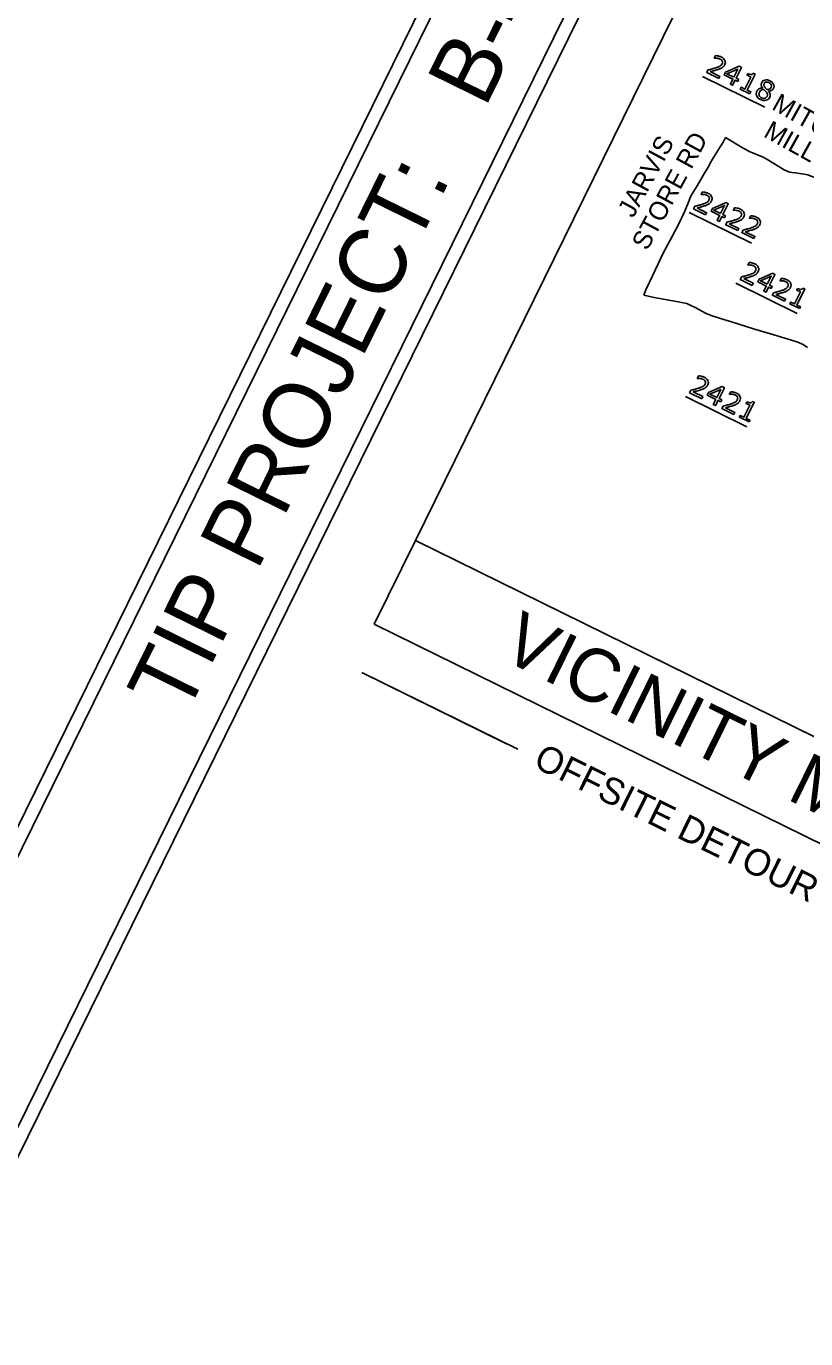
# Model space of a CAD drawing. Extents: x 1428128 to 1430390, y 857947 to 859822.
# Drawn here: x 1428792.5 to 1429086, y 858941.1 to 859435.3 of the extents above; entities that cross this region are included whole.
import ezdxf

# ---------------------------------------------------------------- set-up
doc = ezdxf.new("R2010")
doc.units = 0
for name, color, linetype in [('Old_Level_1', 7, 'Continuous'), ('Sheet Data Field CELL', 7, 'Continuous'), ('Sheet Title CELL', 7, 'Continuous')]:
    doc.layers.add(name, color=color, linetype=linetype)

msp = doc.modelspace()

# ---------------------------------------------------------------- linework, layer by layer
at = {"layer": 'Old_Level_1'}
for p, q in [((1429047.11, 859416.46), (1429070.63, 859404.89)), ((1429042.15, 859365.13), (1429065.62, 859353.58)), ((1429059.72, 859338.55), (1429082.81, 859327.18)), ((1429040.69, 859295.86), (1429063.78, 859284.5)), ((1428918.89, 859191.97), (1428973.38, 859165.16))]:
    msp.add_line(p, q, dxfattribs=at)
for points in [[(1429051.64, 859423.3), (1429051.59, 859423.32), (1429052.06, 859424.27)], [(1429053.28, 859415.66), (1429048.72, 859417.9), (1429049.19, 859418.85)], [(1429050.04, 859418.22), (1429053.66, 859416.44), (1429053.28, 859415.66)], [(1429060.43, 859414.49), (1429059.43, 859414.99), (1429058.49, 859413.09), (1429057.63, 859413.52), (1429058.56, 859415.41), (1429055.33, 859417), (1429055.84, 859418.04), (1429060.97, 859420.23), (1429061.8, 859419.82), (1429059.78, 859415.71), (1429060.78, 859415.22), (1429060.43, 859414.49)], [(1429058.91, 859416.14), (1429060.41, 859419.18), (1429056.3, 859417.42), (1429058.91, 859416.14)], [(1429066.27, 859417.65), (1429066.97, 859417.31), (1429063.98, 859411.24), (1429065.36, 859410.57), (1429065.02, 859409.88)], [(1429065.02, 859409.88), (1429061.38, 859411.67), (1429061.71, 859412.36), (1429063.11, 859411.67), (1429065.33, 859416.18), (1429063.93, 859416.87), (1429064.24, 859417.48)], [(1429069.74, 859412.02), (1429069.76, 859412.04)], [(1429071.97, 859410.91), (1429071.96, 859410.88)], [(1429046.68, 859371.97), (1429046.63, 859371.99), (1429047.1, 859372.94)], [(1429055.47, 859363.16), (1429054.47, 859363.65), (1429053.54, 859361.76), (1429052.67, 859362.18), (1429053.6, 859364.08), (1429050.38, 859365.66), (1429050.89, 859366.7), (1429056.01, 859368.89), (1429056.85, 859368.49), (1429054.82, 859364.38), (1429055.82, 859363.88), (1429055.47, 859363.16)], [(1429048.32, 859364.32), (1429043.76, 859366.57), (1429044.23, 859367.52)], [(1429045.08, 859366.89), (1429048.7, 859365.1), (1429048.32, 859364.32)], [(1429053.96, 859364.8), (1429055.45, 859367.84), (1429051.35, 859366.09), (1429053.96, 859364.8)], [(1429058.8, 859366), (1429058.76, 859366.02), (1429059.22, 859366.97)], [(1429064.87, 859363.02), (1429064.82, 859363.04), (1429065.29, 859363.99)], [(1429060.44, 859358.36), (1429055.88, 859360.6), (1429056.35, 859361.55)], [(1429057.2, 859360.92), (1429060.83, 859359.14), (1429060.44, 859358.36)], [(1429066.51, 859355.37), (1429061.95, 859357.62), (1429062.42, 859358.57)], [(1429063.27, 859357.94), (1429066.89, 859356.15), (1429066.51, 859355.37)], [(1429064.25, 859345.38), (1429064.21, 859345.41), (1429064.67, 859346.35)], [(1429065.89, 859337.74), (1429061.33, 859339.98), (1429061.8, 859340.93)], [(1429062.65, 859340.3), (1429066.28, 859338.52), (1429065.89, 859337.74)], [(1429073.04, 859336.58), (1429072.04, 859337.07), (1429071.11, 859335.17), (1429070.24, 859335.6), (1429071.17, 859337.49), (1429067.95, 859339.08), (1429068.46, 859340.12), (1429073.59, 859342.31), (1429074.42, 859341.9), (1429072.4, 859337.79), (1429073.4, 859337.3), (1429073.04, 859336.58)], [(1429071.53, 859338.22), (1429073.03, 859341.26), (1429068.92, 859339.5), (1429071.53, 859338.22)], [(1429076.38, 859339.42), (1429076.33, 859339.44), (1429076.8, 859340.39)], [(1429078.02, 859331.77), (1429073.46, 859334.02), (1429073.93, 859334.97)], [(1429074.78, 859334.34), (1429078.4, 859332.55), (1429078.02, 859331.77)], [(1429083.7, 859328.98), (1429080.05, 859330.77), (1429080.39, 859331.46), (1429081.79, 859330.77), (1429084.01, 859335.28), (1429082.61, 859335.97), (1429082.91, 859336.58)], [(1429084.94, 859336.75), (1429085.65, 859336.41), (1429082.66, 859330.34), (1429084.03, 859329.67), (1429083.7, 859328.98)], [(1429045.22, 859302.7), (1429045.17, 859302.72), (1429045.64, 859303.67)], [(1429054.01, 859293.89), (1429053.01, 859294.39), (1429052.08, 859292.49), (1429051.21, 859292.92), (1429052.14, 859294.81), (1429048.92, 859296.4), (1429049.43, 859297.44), (1429054.56, 859299.63), (1429055.39, 859299.22), (1429053.37, 859295.11), (1429054.37, 859294.62), (1429054.01, 859293.89)], [(1429046.86, 859295.06), (1429042.3, 859297.3), (1429042.77, 859298.25)], [(1429043.62, 859297.62), (1429047.24, 859295.84), (1429046.86, 859295.06)], [(1429052.5, 859295.54), (1429053.99, 859298.58), (1429049.89, 859296.82), (1429052.5, 859295.54)], [(1429057.35, 859296.74), (1429057.3, 859296.76), (1429057.77, 859297.71)], [(1429065.91, 859294.07), (1429066.61, 859293.72), (1429063.63, 859287.66), (1429065, 859286.98), (1429064.66, 859286.3)], [(1429058.99, 859289.09), (1429054.43, 859291.33), (1429054.9, 859292.29)], [(1429055.75, 859291.65), (1429059.37, 859289.87), (1429058.99, 859289.09)], [(1429064.66, 859286.3), (1429061.02, 859288.09), (1429061.36, 859288.78), (1429062.76, 859288.09), (1429064.98, 859292.6), (1429063.58, 859293.29), (1429063.88, 859293.9)]]:
    msp.add_lwpolyline(points, dxfattribs=at)
for points in [[(1429049.19, 859418.85), (1429049.86, 859419.03), (1429050.54, 859419.2), (1429051.22, 859419.37), (1429051.83, 859419.57), (1429053.11, 859419.98), (1429053.67, 859420.32), (1429054.24, 859420.65), (1429054.52, 859421.23), (1429054.78, 859421.75), (1429054.58, 859422.22), (1429054.38, 859422.68), (1429053.76, 859422.99), (1429053.34, 859423.19), (1429052.79, 859423.28), (1429052.24, 859423.37), (1429051.64, 859423.3)], [(1429052.06, 859424.27), (1429052.46, 859424.27), (1429053.06, 859424.14), (1429053.66, 859424.01), (1429054.16, 859423.76), (1429055.2, 859423.25), (1429055.54, 859422.46), (1429055.88, 859421.67), (1429055.46, 859420.82), (1429055.27, 859420.43), (1429055.01, 859420.15), (1429054.75, 859419.87), (1429054.41, 859419.66), (1429054.1, 859419.47), (1429053.73, 859419.31), (1429053.36, 859419.16), (1429052.86, 859419), (1429052.14, 859418.76), (1429051.41, 859418.57), (1429050.67, 859418.38), (1429050.04, 859418.22)], [(1429064.24, 859417.48), (1429064.52, 859417.34), (1429064.87, 859417.23), (1429065.22, 859417.12), (1429065.43, 859417.13), (1429065.69, 859417.14), (1429065.9, 859417.25), (1429066.1, 859417.37), (1429066.27, 859417.65)], [(1429069.76, 859412.04), (1429069.36, 859412.6), (1429069.26, 859413.07), (1429069.17, 859413.54), (1429069.43, 859414.06), (1429069.8, 859414.82), (1429070.67, 859415.02), (1429071.55, 859415.22), (1429072.51, 859414.74), (1429073.52, 859414.25), (1429073.88, 859413.47), (1429074.24, 859412.69), (1429073.88, 859411.94), (1429073.65, 859411.49), (1429073.15, 859411.19), (1429072.65, 859410.89), (1429071.97, 859410.91)], [(1429072.98, 859412.37), (1429073.22, 859412.85), (1429072.99, 859413.33), (1429072.76, 859413.8), (1429072.18, 859414.08), (1429071.61, 859414.36), (1429071.11, 859414.27), (1429070.61, 859414.18), (1429070.38, 859413.72), (1429070.22, 859413.39), (1429070.29, 859413.06), (1429070.36, 859412.74), (1429070.64, 859412.37), (1429070.76, 859412.21), (1429071.01, 859411.92), (1429071.26, 859411.63), (1429071.52, 859411.4), (1429072.12, 859411.48), (1429072.45, 859411.71), (1429072.78, 859411.95), (1429072.98, 859412.37)], [(1429072.44, 859408.56), (1429072.01, 859407.69), (1429071.04, 859407.44), (1429070.08, 859407.2), (1429069.05, 859407.71), (1429067.95, 859408.24), (1429067.58, 859409.13), (1429067.21, 859410.01), (1429067.64, 859410.89), (1429067.92, 859411.46), (1429068.47, 859411.75), (1429069.02, 859412.04), (1429069.74, 859412.02)], [(1429071.47, 859408.93), (1429071.67, 859409.35), (1429071.61, 859409.69), (1429071.55, 859410.03), (1429071.14, 859410.54), (1429070.98, 859410.75), (1429070.77, 859410.96), (1429070.56, 859411.17), (1429070.21, 859411.53), (1429069.7, 859411.51), (1429069.26, 859411.25), (1429068.83, 859410.99), (1429068.6, 859410.51), (1429068.3, 859409.9), (1429068.52, 859409.3), (1429068.75, 859408.69), (1429069.39, 859408.38), (1429070.05, 859408.05), (1429070.61, 859408.2), (1429071.18, 859408.34), (1429071.47, 859408.93)], [(1429071.96, 859410.88), (1429072.46, 859410.3), (1429072.6, 859409.74), (1429072.74, 859409.17), (1429072.44, 859408.56)], [(1429044.23, 859367.52), (1429044.9, 859367.69), (1429045.58, 859367.86), (1429046.26, 859368.03), (1429046.87, 859368.23), (1429048.15, 859368.64), (1429048.72, 859368.98), (1429049.28, 859369.32), (1429049.56, 859369.89), (1429049.82, 859370.42), (1429049.62, 859370.88), (1429049.42, 859371.35), (1429048.8, 859371.65), (1429048.39, 859371.86), (1429047.83, 859371.95), (1429047.28, 859372.04), (1429046.68, 859371.97)], [(1429047.1, 859372.94), (1429047.5, 859372.94), (1429048.1, 859372.8), (1429048.7, 859372.67), (1429049.2, 859372.42), (1429050.24, 859371.91), (1429050.58, 859371.13), (1429050.92, 859370.34), (1429050.5, 859369.48), (1429050.31, 859369.1), (1429050.05, 859368.82), (1429049.79, 859368.53), (1429049.46, 859368.33), (1429049.14, 859368.13), (1429048.77, 859367.98), (1429048.4, 859367.83), (1429047.9, 859367.66), (1429047.18, 859367.43), (1429046.45, 859367.24), (1429045.71, 859367.04), (1429045.08, 859366.89)], [(1429056.35, 859361.55), (1429057.03, 859361.72), (1429057.71, 859361.9), (1429058.38, 859362.07), (1429058.99, 859362.27), (1429060.28, 859362.68), (1429060.84, 859363.01), (1429061.41, 859363.35), (1429061.69, 859363.92), (1429061.95, 859364.45), (1429061.75, 859364.92), (1429061.55, 859365.38), (1429060.92, 859365.69), (1429060.51, 859365.89), (1429059.96, 859365.98), (1429059.41, 859366.07), (1429058.8, 859366)], [(1429059.22, 859366.97), (1429059.62, 859366.97), (1429060.22, 859366.84), (1429060.82, 859366.71), (1429061.33, 859366.46), (1429062.36, 859365.95), (1429062.71, 859365.16), (1429063.05, 859364.37), (1429062.63, 859363.52), (1429062.44, 859363.13), (1429062.18, 859362.85), (1429061.92, 859362.57), (1429061.58, 859362.36), (1429061.27, 859362.17), (1429060.9, 859362.01), (1429060.53, 859361.86), (1429060.03, 859361.7), (1429059.31, 859361.46), (1429058.57, 859361.27), (1429057.84, 859361.08), (1429057.2, 859360.92)], [(1429065.29, 859363.99), (1429065.69, 859363.99), (1429066.29, 859363.85), (1429066.89, 859363.72), (1429067.39, 859363.47), (1429068.43, 859362.96), (1429068.77, 859362.18), (1429069.11, 859361.39), (1429068.69, 859360.53), (1429068.5, 859360.15), (1429068.24, 859359.87), (1429067.98, 859359.58), (1429067.65, 859359.38), (1429067.33, 859359.18), (1429066.96, 859359.03), (1429066.59, 859358.88), (1429066.09, 859358.71), (1429065.37, 859358.48), (1429064.64, 859358.29), (1429063.9, 859358.09), (1429063.27, 859357.94)], [(1429062.42, 859358.57), (1429063.09, 859358.74), (1429063.77, 859358.91), (1429064.45, 859359.08), (1429065.06, 859359.28), (1429066.34, 859359.7), (1429066.91, 859360.03), (1429067.47, 859360.37), (1429067.75, 859360.94), (1429068.01, 859361.47), (1429067.81, 859361.93), (1429067.61, 859362.4), (1429066.99, 859362.7), (1429066.57, 859362.91), (1429066.02, 859363), (1429065.47, 859363.09), (1429064.87, 859363.02)], [(1429061.8, 859340.93), (1429062.48, 859341.11), (1429063.15, 859341.28), (1429063.83, 859341.45), (1429064.44, 859341.65), (1429065.73, 859342.06), (1429066.29, 859342.4), (1429066.86, 859342.73), (1429067.14, 859343.31), (1429067.4, 859343.83), (1429067.19, 859344.3), (1429066.99, 859344.77), (1429066.37, 859345.07), (1429065.96, 859345.27), (1429065.41, 859345.37), (1429064.86, 859345.46), (1429064.25, 859345.38)], [(1429064.67, 859346.35), (1429065.07, 859346.35), (1429065.67, 859346.22), (1429066.27, 859346.09), (1429066.78, 859345.84), (1429067.81, 859345.33), (1429068.15, 859344.54), (1429068.5, 859343.75), (1429068.08, 859342.9), (1429067.89, 859342.52), (1429067.63, 859342.23), (1429067.37, 859341.95), (1429067.03, 859341.74), (1429066.72, 859341.55), (1429066.35, 859341.4), (1429065.97, 859341.24), (1429065.47, 859341.08), (1429064.76, 859340.84), (1429064.02, 859340.65), (1429063.29, 859340.46), (1429062.65, 859340.3)], [(1429073.93, 859334.97), (1429074.6, 859335.14), (1429075.28, 859335.31), (1429075.96, 859335.48), (1429076.57, 859335.68), (1429077.85, 859336.1), (1429078.42, 859336.43), (1429078.98, 859336.77), (1429079.26, 859337.34), (1429079.52, 859337.87), (1429079.32, 859338.33), (1429079.12, 859338.8), (1429078.5, 859339.1), (1429078.09, 859339.31), (1429077.53, 859339.4), (1429076.98, 859339.49), (1429076.38, 859339.42)], [(1429076.8, 859340.39), (1429077.2, 859340.39), (1429077.8, 859340.25), (1429078.4, 859340.12), (1429078.9, 859339.87), (1429079.94, 859339.36), (1429080.28, 859338.58), (1429080.62, 859337.79), (1429080.2, 859336.93), (1429080.01, 859336.55), (1429079.75, 859336.27), (1429079.49, 859335.98), (1429079.16, 859335.78), (1429078.84, 859335.58), (1429078.47, 859335.43), (1429078.1, 859335.28), (1429077.6, 859335.11), (1429076.88, 859334.88), (1429076.15, 859334.69), (1429075.41, 859334.5), (1429074.78, 859334.34)], [(1429082.91, 859336.58), (1429083.2, 859336.44), (1429083.55, 859336.33), (1429083.9, 859336.22), (1429084.11, 859336.23), (1429084.37, 859336.24), (1429084.58, 859336.35), (1429084.78, 859336.47), (1429084.94, 859336.75)], [(1429042.77, 859298.25), (1429043.45, 859298.43), (1429044.12, 859298.6), (1429044.8, 859298.77), (1429045.41, 859298.97), (1429046.69, 859299.38), (1429047.26, 859299.72), (1429047.82, 859300.05), (1429048.11, 859300.63), (1429048.36, 859301.15), (1429048.16, 859301.62), (1429047.96, 859302.08), (1429047.34, 859302.39), (1429046.93, 859302.59), (1429046.38, 859302.68), (1429045.82, 859302.77), (1429045.22, 859302.7)], [(1429045.64, 859303.67), (1429046.04, 859303.67), (1429046.64, 859303.54), (1429047.24, 859303.41), (1429047.74, 859303.16), (1429048.78, 859302.65), (1429049.12, 859301.86), (1429049.47, 859301.07), (1429049.05, 859300.22), (1429048.86, 859299.83), (1429048.6, 859299.55), (1429048.34, 859299.27), (1429048, 859299.06), (1429047.68, 859298.87), (1429047.31, 859298.71), (1429046.94, 859298.56), (1429046.44, 859298.4), (1429045.72, 859298.16), (1429044.99, 859297.97), (1429044.26, 859297.78), (1429043.62, 859297.62)], [(1429054.9, 859292.29), (1429055.57, 859292.46), (1429056.25, 859292.63), (1429056.93, 859292.8), (1429057.54, 859293), (1429058.82, 859293.41), (1429059.38, 859293.75), (1429059.95, 859294.09), (1429060.23, 859294.66), (1429060.49, 859295.18), (1429060.29, 859295.65), (1429060.09, 859296.12), (1429059.47, 859296.42), (1429059.05, 859296.62), (1429058.5, 859296.72), (1429057.95, 859296.81), (1429057.35, 859296.74)], [(1429057.77, 859297.71), (1429058.17, 859297.71), (1429058.77, 859297.57), (1429059.37, 859297.44), (1429059.87, 859297.19), (1429060.91, 859296.68), (1429061.25, 859295.89), (1429061.59, 859295.11), (1429061.17, 859294.25), (1429060.98, 859293.87), (1429060.72, 859293.58), (1429060.46, 859293.3), (1429060.12, 859293.1), (1429059.81, 859292.9), (1429059.44, 859292.75), (1429059.07, 859292.59), (1429058.57, 859292.43), (1429057.85, 859292.19), (1429057.12, 859292), (1429056.38, 859291.81), (1429055.75, 859291.65)], [(1429063.88, 859293.9), (1429064.17, 859293.76), (1429064.52, 859293.65), (1429064.86, 859293.54), (1429065.08, 859293.54), (1429065.34, 859293.55), (1429065.55, 859293.67), (1429065.75, 859293.78), (1429065.91, 859294.07)]]:
    msp.add_open_spline(points, degree=3, dxfattribs=at)
at = {"layer": 'Sheet Title CELL'}
for p, q in [((1428623.95, 858684.82), (1429065.46, 859582.08)), ((1428710.12, 858848.61), (1429069.94, 859579.87)), ((1428939, 859241.66), (1429080.28, 859528.78)), ((1429217.15, 859104.79), (1428939, 859241.66)), ((1428918.91, 859191.96), (1428977.58, 859163.09))]:
    msp.add_line(p, q, dxfattribs=at)
for points in [[(1429022.8, 859608.64), (1428576.88, 858702.41)], [(1429022.8, 859608.64), (1428576.88, 858702.41)], [(1429025.09, 859601.94), (1428583.58, 858704.69)], [(1429025.04, 859334.1), (1429025.85, 859336.1), (1429028.47, 859341.61), (1429032.38, 859349.83), (1429035.84, 859356.41), (1429038.25, 859360.95), (1429040.32, 859365.43), (1429041.83, 859369.11), (1429042.68, 859371.11), (1429043.29, 859372.18), (1429045.12, 859375.18), (1429047.53, 859379.39), (1429049.25, 859382.27), (1429050.49, 859384.6), (1429051.3, 859385.9), (1429053.84, 859389.93), (1429054.74, 859391.39), (1429055.75, 859393.46)], [(1429055.75, 859393.46), (1429062.4, 859389.46), (1429065.08, 859388.06), (1429069.93, 859386.03), (1429071.79, 859385.08), (1429077.86, 859381.29), (1429079.94, 859380.33), (1429080.76, 859380.2), (1429082.31, 859380.07), (1429083.7, 859379.92), (1429085.4, 859379.65), (1429086.76, 859379.31), (1429088.37, 859378.78), (1429090.08, 859378.24), (1429092.8, 859377.13), (1429095.18, 859376.06), (1429097.39, 859374.95), (1429098.96, 859374.14), (1429101.01, 859372.97), (1429102.13, 859372.36), (1429106.77, 859369.68), (1429108.85, 859368.7), (1429111.63, 859367.82)], [(1429080.6, 859317.15), (1429078.16, 859317.82), (1429072.72, 859319.47), (1429066.32, 859321.33), (1429058.05, 859324.07), (1429053.96, 859325.27), (1429050.44, 859326.42), (1429048.27, 859327.25), (1429044.65, 859329.27), (1429042.47, 859330.34), (1429041.27, 859330.87), (1429039.23, 859331.32), (1429037.4, 859331.66), (1429035.26, 859332.04), (1429028.98, 859333.22), (1429025.04, 859334.1)], [(1429086.65, 859314.38), (1429085.03, 859315.44), (1429083.07, 859316.35), (1429080.6, 859317.15)]]:
    msp.add_lwpolyline(points, dxfattribs=at)
msp.add_lwpolyline([(1428939, 859241.66), (1429217.15, 859104.79), (1429201.66, 859073.32), (1428923.51, 859210.19)], close=True, dxfattribs=at)

# ---------------------------------------------------------------- texts
at = {"layer": 'Old_Level_1'}
for s, rotation, p in [('MITCHELL', 330.9009, (1429072.81, 859404.25)), ('MILL RD.', 330.9009, (1429069.73, 859393.94)), ('JARVIS', 61.531, (1429021.03, 859362.81)), ('STORE RD', 61.531, (1429026.29, 859350.49))]:
    msp.add_text(s, height=7, rotation=rotation, dxfattribs=at).set_placement(p)
at = {"layer": 'Sheet Data Field CELL'}
for s, height, p in [('VICINITY MAP', 20, (1428970.38, 859197.6)), ('OFFSITE DETOUR', 10, (1428982.96, 859156.62))]:
    msp.add_text(s, height=height, rotation=333.8001, dxfattribs=at).set_placement(p)
at = {"layer": 'Sheet Title CELL'}
for s, p in [('B-4846', (1428965.2, 859404.11)), ('TIP PROJECT:', (1428852.36, 859174.81))]:
    msp.add_text(s, height=25, rotation=63.8001, dxfattribs=at).set_placement(p)

doc.saveas('drawing.dxf')
